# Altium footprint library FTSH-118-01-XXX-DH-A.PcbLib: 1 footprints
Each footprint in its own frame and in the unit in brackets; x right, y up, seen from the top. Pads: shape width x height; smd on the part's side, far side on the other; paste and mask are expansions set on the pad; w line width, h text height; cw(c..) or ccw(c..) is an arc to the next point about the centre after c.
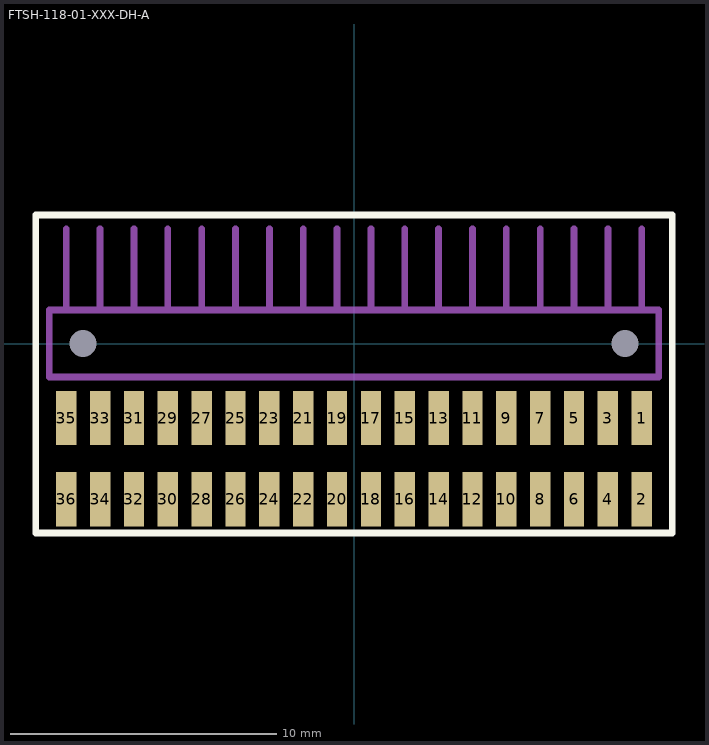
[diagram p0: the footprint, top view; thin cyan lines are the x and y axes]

## FTSH-118-01-XXX-DH-A [mil]
pads (38):
  rect 30x80 smd mask+2: 1(425,-110) 2(425,-230) 3(375,-110) 4(375,-230) 5(325,-110) 6(325,-230) 7(275,-110) 8(275,-230) 9(225,-110) 10(225,-230) 11(175,-110) 12(175,-230) 13(125,-110) 14(125,-230) 15(75,-110) 16(75,-230) 17(25,-110) 18(25,-230) 19(-25,-110) 20(-25,-230) 21(-75,-110) 22(-75,-230) 23(-125,-110) 24(-125,-230) 25(-175,-110) 26(-175,-230) 27(-225,-110) 28(-225,-230) 29(-275,-110) 30(-275,-230) 31(-325,-110) 32(-325,-230) 33(-375,-110) 34(-375,-230) 35(-425,-110) 36(-425,-230)
  round 0 hole 40 unplated: 37(400,0) 38(-400,0)
Top Overlay:
  lines w10: -470,-280 470,-280 470,190 -470,190 -470,-280
Mechanical 1:
  lines w10: -425,49.5 -425,169.5 ; -375,49.5 -375,169.5 ; -325,49.5 -325,169.5 ; -275,49.5 -275,169.5 ; -225,49.5 -225,169.5 ; -175,49.5 -175,169.5 ; -125,49.5 -125,169.5 ; -75,49.5 -75,169.5 ; -25,49.5 -25,169.5 ; 25,49.5 25,169.5 ; 75,49.5 75,169.5 ; 125,49.5 125,169.5 ; 175,49.5 175,169.5 ; 225,49.5 225,169.5 ; 275,49.5 275,169.5 ; 325,49.5 325,169.5 ; 375,49.5 375,169.5 ; 425,49.5 425,169.5 ; -450,-49.5 450,-49.5 450,49.5 -450,49.5 -450,-49.5
  text "J1" at -17.57,-18 h30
